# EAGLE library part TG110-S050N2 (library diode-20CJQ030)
Halo's TG110-S050N2 ULTRA-Series, 16 Pin SOIC 10/100BASE-TX Magnetic Modules Description: HALO Electronics has developed the ULTRA-series of 16 pin SOIC Isolation Modules to meet the requirements of IEEE 802.3 for 10/100BASE-TX and ATM155 applications. Designed to provide a significant real estate reduction at the lowest price. Standard devices are available for all Phy's. Please visit our web site to select the correct device for the corresponding Phy. Please send any comments to: messi@users.sourceforge.net
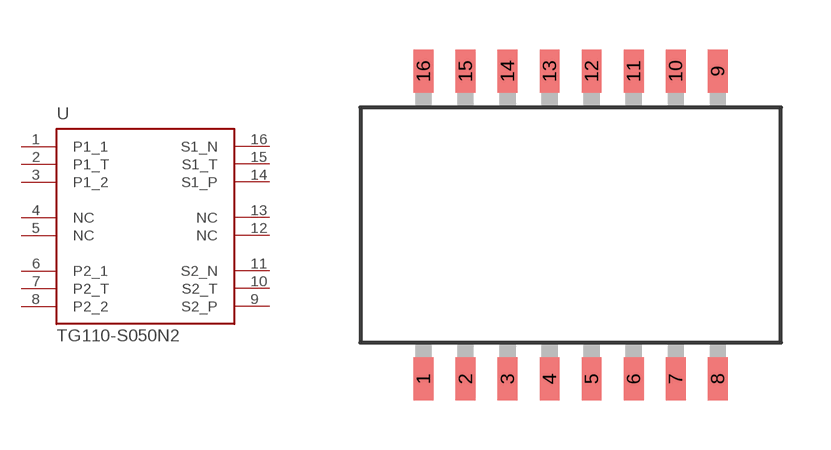
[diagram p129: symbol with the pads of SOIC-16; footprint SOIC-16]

Designator prefix U

## TG110-S050N2  [SOIC-16]
1  P1_1  pas
2  P1_T  pas
3  P1_2  pas
4  NC  pas
5  NC  pas
6  P2_1  pas
7  P2_T  pas
8  P2_2  pas
9  S2_P  pas
10  S2_T  pas
11  S2_N  pas
12  NC  pas
13  NC  pas
14  S1_P  pas
15  S1_T  pas
16  S1_N  pas

## Footprint SOIC-16 (pad centres in mm)
smd 0.6 x 1.3: 1 -4.445,-4.65; 2 -3.175,-4.65; 3 -1.905,-4.65; 4 -0.635,-4.65; 5 0.635,-4.65; 6 1.905,-4.65; 7 3.175,-4.65; 8 4.445,-4.65; 9 4.445,4.65; 10 3.175,4.65; 11 1.905,4.65; 12 0.635,4.65; 13 -0.635,4.65; 14 -1.905,4.65; 15 -3.175,4.65; 16 -4.445,4.65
